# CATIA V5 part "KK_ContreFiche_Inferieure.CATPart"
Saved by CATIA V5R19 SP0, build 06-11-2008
Part number: Contre fiche inferieure
Bounding box of the stored display mesh (mm): x -1052.971 to 294.779, y 568.502 to 1011.394, z -1727.978 to -839.243
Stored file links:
  G:\Khaled_CFAO_2011\ST2M\ST2M_GR2\aboulegue\Khaled\CAD_thinkMOTION\KK_ContreFiche_Inferieure.CATPart
  G:\Khaled_CFAO_2011\ST2M\ST2M_GR2\aboulegue\Khaled\CAD_thinkMOTION\KK_Train_Atterrissage.CATProduct
  G:\Khaled_CFAO_2011\ST2M\ST2M_GR2\aboulegue\CFAO_aboulegue\CFAO_aboulegue_fichiers_catia\Squelette_tige_verin_deverouillage.CATPart
  G:\Khaled_CFAO_2011\ST2M\ST2M_GR2\aboulegue\Khaled\CAD_thinkMOTION\KK_SqueletteContre_FicheInferieure.CATPart
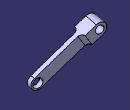
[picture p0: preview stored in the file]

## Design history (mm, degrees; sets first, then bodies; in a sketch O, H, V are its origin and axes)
Set1
  Plane1 "Plan reference contre fiche superieue": linked copy from another document
  Point1: linked copy from another document
  Point2 "Point.15": linked copy from another document
  Line1: linked copy from another document
Body1 (main body)
  Sketch1 on Plane1, origin (95.3692, 652.5403, 0), H (0.9817, -0.1905, 0), V (0, 0, 1)
    construction line L1 (-1013.8369, -967.2204) -> (65.8361, -1600)
    point P1 (-1013.8369, -967.2204)
    point P2 (65.8361, -1600)
    line L2 (-949.1148, -856.7891) -> (130.5582, -1489.5688)
    line L3 (1.1141, -1710.4312) -> (-1078.5589, -1077.6516)
    arc A1 centre (65.8361, -1600) radius 128 from (130.5582, -1489.5688) to (1.1141, -1710.4312) cw
    arc A2 centre (-1013.8369, -967.2204) radius 128 from (-1078.5589, -1077.6516) to (-949.1148, -856.7891) cw
    reference projected point E1 (65.8361, -1600) from Point1
    reference projected point E2 (-1013.8369, -967.2204) from Point2
    distance L1 L2 = 128
    tangency: A1 L2, A2 L2, A1 L3, A2 L3
    coincidence: P2 E1, P1 E2
  Pad1: profile Sketch1, direction (-0.1905, -0.9817, 0), length 144, mirrored extent
  Sketch2 on face of Pad1 from Sketch1.L2, origin (-620.982, 92.7993, -1063.3821), H (0.1586, 0.9872, 0.0189), V (-0.8535, 0.1274, 0.5053)
    line L1 (739.7648, 141.5116) -> (919.6383, 134.7658)
    line L2 (919.6383, 134.7658) -> (874.6667, -1064.3912)
    line L3 (874.6667, -1064.3912) -> (694.7932, -1057.6454)
    line L4 (694.7932, -1057.6454) -> (739.7648, 141.5116)
    reference projected line E1 through (0.2393, -843.4657) direction (-0.9993, 0.0375) from axis of face of Pad1 from Sketch1.A1
    reference projected line E2 (700.7562, 382.1658) -> (654.3813, -854.4112) from Line1
    line L5 (463.9586, 151.855) -> (643.8322, 145.1093)
    line L6 (643.8322, 145.1093) -> (598.8606, -1054.0477)
    line L7 (598.8606, -1054.0477) -> (418.9871, -1047.302)
    line L8 (418.9871, -1047.302) -> (463.9586, 151.855)
    reference projected line E3 (700.7562, 382.1658) -> (654.3813, -854.4112) from Line1
    reference projected line E4 through (0.2393, -843.4657) direction (-0.9993, 0.0375) from axis of face of Pad1 from Sketch1.A1
    reference projected line E5 (700.7562, 382.1658) -> (654.3813, -854.4112) from Line1
    reference projected line E6 (700.7562, 382.1658) -> (654.3813, -854.4112) from Line1
    distance L1 E1 = 1012
    length L2 = 1200
    distance E2 L4 = 48
    length L3 = 180
    length L8 = 1200
    length L7 = 180
    distance E3 L6 = 48
    distance L5 E4 = 1012
    parallelism: L4 E5, L6 E6, L8 L6, L2 L4, L7 L5, L1 L3
    perpendicularity: L1 L4, L5 L6
  Pocket1: profile Sketch2, direction (-0.4964, 0.0963, -0.8627), through (limit type 3)
  Fillet1: radius 80, conic ratio 0.3, on edge [face of Pocket1 from Sketch2.L5 | face of Pocket1 from Sketch2.L6]
  Fillet2: radius 80, conic ratio 0.3, on edge [face of Pocket1 from Sketch2.L4 | face of Pocket1 from Sketch2.L1]
  Sketch3 on face of Pocket1 from Sketch2.L6, origin (88.2759, 605.0214, 0), H (0.9817, -0.1905, 0), V (0, 0, 1)
    circle A1 centre (63.7483, -1600) radius 96
    reference projected arc E1 centre (63.7483, -1600) radius 128 from (-1.3335, -1710.2196) to (128.8302, -1489.7804) ccw from edge [face of Pad1 from Sketch1.A1 | face of Pocket1 from Sketch2.L6]
    radius A1 = 96
    concentricity: E1 A1
  Pocket2: profile Sketch3, direction (-0.1905, -0.9817, 0), through (limit type 3)
  Sketch4 on end face of Pad1, origin (74.0891, 509.9837, 0), H (0.9817, -0.1905, 0), V (0, 0, 1)
    circle A1 centre (-1020.1002, -967.2204) radius 80
    reference projected arc E1 centre (-1020.1002, -967.2204) radius 128 from (-955.0184, -857.0008) to (-1085.182, -1077.44) ccw from edge [face of Pad1 from Sketch1.A2 | end face of Pad1]
    radius A1 = 80
    concentricity: A1 E1
  Pocket3: profile Sketch4, direction (0.1905, 0.9817, 0), through (limit type 3)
